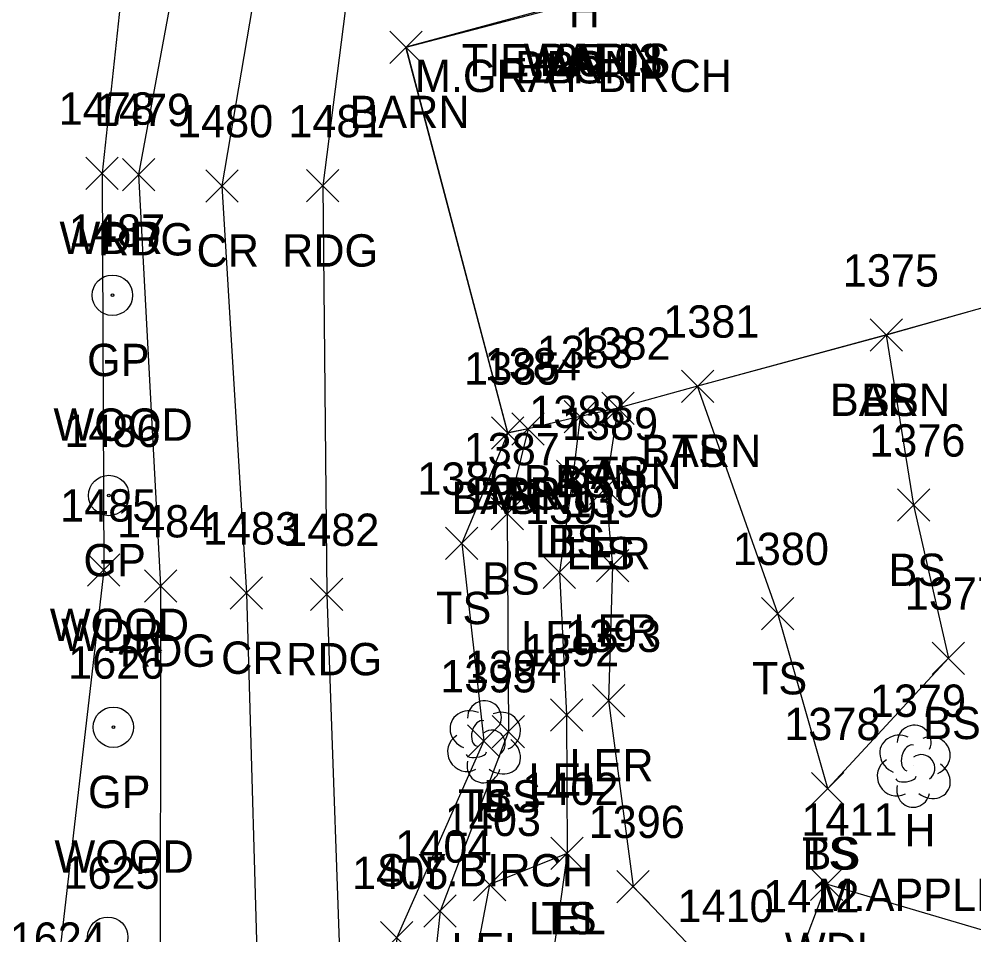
# Model space of a CAD drawing. Extents: x 1512665 to 1513714, y 110636 to 112816.
# Drawn here: x 1513105.8 to 1513164.9, y 110851.6 to 110908.3 of the extents above; entities that cross this region are included whole.
import ezdxf

# ---------------------------------------------------------------- set-up
doc = ezdxf.new("R2010")
doc.units = 0
for name, color, linetype in [('C_C', 7, 'Continuous'), ('L_A', 7, 'Continuous'), ('L_C', 7, 'Continuous'), ('L_I', 7, 'Continuous'), ('L_TIC', 7, 'Continuous'), ('LARO', 7, 'Continuous'), ('LAWA', 7, 'Continuous'), ('LBC', 7, 'Continuous'), ('LELB', 7, 'Continuous'), ('Level 13', 7, 'Continuous'), ('LTD', 7, 'Continuous'), ('P_A', 7, 'Continuous'), ('P_I', 7, 'Continuous'), ('P_TIC', 7, 'Continuous'), ('PEU', 7, 'Continuous'), ('PRC', 7, 'Continuous'), ('R_A', 7, 'Continuous'), ('R_C', 7, 'Continuous'), ('R_I', 7, 'Continuous'), ('RGP', 7, 'Continuous')]:
    doc.layers.add(name, color=color, linetype=linetype)

msp = doc.modelspace()

# ---------------------------------------------------------------- linework, layer by layer
at = {"layer": 'L_TIC'}
for points in [[(1513128.773, 110905.51), (1513130.773, 110907.51)], [(1513130.773, 110905.51), (1513128.773, 110907.51)], [(1513128.773, 110905.51), (1513130.773, 110907.51)], [(1513130.773, 110905.51), (1513128.773, 110907.51)], [(1513109.982, 110897.719), (1513111.982, 110899.719)], [(1513111.982, 110897.719), (1513109.982, 110899.719)], [(1513158.494, 110887.706), (1513160.494, 110889.706)], [(1513160.494, 110887.706), (1513158.494, 110889.706)], [(1513158.494, 110887.706), (1513160.494, 110889.706)], [(1513160.494, 110887.706), (1513158.494, 110889.706)], [(1513146.816, 110884.548), (1513148.816, 110886.548)], [(1513148.816, 110884.548), (1513146.816, 110886.548)], [(1513146.816, 110884.548), (1513148.816, 110886.548)], [(1513148.816, 110884.548), (1513146.816, 110886.548)], [(1513141.89, 110883.183), (1513143.89, 110885.183)], [(1513143.89, 110883.183), (1513141.89, 110885.183)], [(1513141.89, 110883.183), (1513143.89, 110885.183)], [(1513143.89, 110883.183), (1513141.89, 110885.183)], [(1513139.558, 110882.667), (1513141.558, 110884.667)], [(1513141.558, 110882.667), (1513139.558, 110884.667)], [(1513139.558, 110882.667), (1513141.558, 110884.667)], [(1513141.558, 110882.667), (1513139.558, 110884.667)], [(1513135.07, 110881.644), (1513137.07, 110883.644)], [(1513137.07, 110881.644), (1513135.07, 110883.644)], [(1513135.07, 110881.644), (1513137.07, 110883.644)], [(1513137.07, 110881.644), (1513135.07, 110883.644)], [(1513136.337, 110881.904), (1513138.337, 110883.904)], [(1513138.337, 110881.904), (1513136.337, 110883.904)], [(1513136.337, 110881.904), (1513138.337, 110883.904)], [(1513138.337, 110881.904), (1513136.337, 110883.904)], [(1513139.1, 110878.963), (1513141.1, 110880.963)], [(1513141.1, 110878.963), (1513139.1, 110880.963)], [(1513139.1, 110878.963), (1513141.1, 110880.963)], [(1513141.1, 110878.963), (1513139.1, 110880.963)], [(1513141.127, 110878.225), (1513143.127, 110880.225)], [(1513143.127, 110878.225), (1513141.127, 110880.225)], [(1513141.127, 110878.225), (1513143.127, 110880.225)], [(1513143.127, 110878.225), (1513141.127, 110880.225)], [(1513160.183, 110877.191), (1513162.183, 110879.191)], [(1513162.183, 110877.191), (1513160.183, 110879.191)], [(1513135.042, 110876.657), (1513137.042, 110878.657)], [(1513137.042, 110876.657), (1513135.042, 110878.657)], [(1513132.23, 110874.829), (1513134.23, 110876.829)], [(1513134.23, 110874.829), (1513132.23, 110876.829)], [(1513110.08, 110873.171), (1513112.08, 110875.171)], [(1513112.08, 110873.171), (1513110.08, 110875.171)], [(1513141.558, 110873.446), (1513143.558, 110875.446)], [(1513143.558, 110873.446), (1513141.558, 110875.446)], [(1513138.267, 110873.032), (1513140.267, 110875.032)], [(1513140.267, 110873.032), (1513138.267, 110875.032)], [(1513151.775, 110870.485), (1513153.775, 110872.485)], [(1513153.775, 110870.485), (1513151.775, 110872.485)], [(1513162.332, 110867.72), (1513164.332, 110869.72)], [(1513164.332, 110867.72), (1513162.332, 110869.72)], [(1513141.308, 110865.107), (1513143.308, 110867.107)], [(1513143.308, 110865.107), (1513141.308, 110867.107)], [(1513138.714, 110864.221), (1513140.714, 110866.221)], [(1513140.714, 110864.221), (1513138.714, 110866.221)], [(1513135.12, 110863.188), (1513137.12, 110865.188)], [(1513137.12, 110863.188), (1513135.12, 110865.188)], [(1513133.591, 110862.608), (1513135.591, 110864.608)], [(1513135.591, 110862.608), (1513133.591, 110864.608)], [(1513154.872, 110859.655), (1513156.872, 110861.655)], [(1513156.872, 110859.655), (1513154.872, 110861.655)], [(1513154.872, 110859.655), (1513156.872, 110861.655)], [(1513156.872, 110859.655), (1513154.872, 110861.655)], [(1513138.746, 110855.646), (1513140.746, 110857.646)], [(1513140.746, 110855.646), (1513138.746, 110857.646)], [(1513138.746, 110855.646), (1513140.746, 110857.646)], [(1513140.746, 110855.646), (1513138.746, 110857.646)], [(1513133.95, 110853.724), (1513135.95, 110855.724)], [(1513135.95, 110853.724), (1513133.95, 110855.724)], [(1513154.8, 110853.743), (1513156.8, 110855.743)], [(1513156.8, 110853.743), (1513154.8, 110855.743)], [(1513142.826, 110853.603), (1513144.826, 110855.603)], [(1513144.826, 110853.603), (1513142.826, 110855.603)], [(1513130.893, 110852.079), (1513132.893, 110854.079)], [(1513132.893, 110852.079), (1513130.893, 110854.079)], [(1513128.213, 110850.444), (1513130.213, 110852.444)], [(1513130.213, 110850.444), (1513128.213, 110852.444)]]:
    msp.add_lwpolyline(points, dxfattribs=at)
at = {"layer": 'LARO'}
for points in [[(1513140.1, 110879.963), (1513139.267, 110874.032), (1513139.714, 110865.221), (1513139.746, 110856.646), (1513134.95, 110854.724), (1513132.21, 110840.272), (1513133.616, 110832.794), (1513134.843, 110824.823), (1513139.129, 110826.282)], [(1513142.127, 110879.225), (1513142.558, 110874.446), (1513142.308, 110866.107), (1513143.826, 110854.603), (1513148.788, 110849.402), (1513154.003, 110849.999), (1513164.386, 110843.715), (1513159.063, 110832.169), (1513158.033, 110824.358), (1513152.454, 110822.764), (1513147.819, 110826.13), (1513139.129, 110826.282)]]:
    msp.add_lwpolyline(points, dxfattribs=at)
at = {"layer": 'LAWA'}
for points in [[(1513113.578, 110922.99), (1513110.982, 110898.719), (1513111.08, 110874.171), (1513108.004, 110847.38), (1513106.159, 110836.973), (1513101.969, 110832.474), (1513101.106, 110831.183), (1513095.313, 110829.256)], [(1513169.909, 110850.574), (1513155.8, 110854.743), (1513154.003, 110849.999), (1513151.762, 110839.769), (1513150.998, 110833.435), (1513152.454, 110822.764), (1513150.034, 110815.279), (1513136.759, 110804.589), (1513129.365, 110796.508), (1513125.79, 110797.836), (1513115.011, 110789.722), (1513110.226, 110788.604), (1513101.86, 110785.924), (1513106.089, 110777.421), (1513109.383, 110771.51), (1513113.636, 110761.19), (1513120.116, 110747.897), (1513117.812, 110736.666), (1513111.118, 110720.921), (1513118.271, 110709.907)]]:
    msp.add_lwpolyline(points, dxfattribs=at)
at = {"layer": 'LBC'}
for points in [[(1513141.517, 110909.732), (1513161.13, 110914.731), (1513177.091, 110919.233), (1513179.116, 110918.457), (1513186.213, 110896.595), (1513183.81, 110895.789), (1513180.342, 110894.907), (1513175.354, 110893.195), (1513159.494, 110888.706), (1513147.816, 110885.548), (1513142.89, 110884.183), (1513140.558, 110883.667), (1513137.337, 110882.904), (1513136.07, 110882.644), (1513129.773, 110906.51)], [(1513141.517, 110909.732), (1513140.02, 110909.272), (1513129.773, 110906.51)]]:
    msp.add_lwpolyline(points, dxfattribs=at)
at = {"layer": 'LELB'}
for points in [[(1513159.494, 110888.706), (1513161.183, 110878.191), (1513163.332, 110868.72), (1513155.872, 110860.655)], [(1513155.872, 110860.655), (1513152.775, 110871.485), (1513147.816, 110885.548)], [(1513142.89, 110884.183), (1513142.127, 110879.225)], [(1513140.558, 110883.667), (1513140.1, 110879.963)], [(1513137.337, 110882.904), (1513136.042, 110877.657), (1513136.12, 110864.188), (1513131.893, 110853.079), (1513130.46, 110839.891), (1513131.567, 110832.675), (1513130.921, 110819.726), (1513129.422, 110808.1), (1513125.79, 110797.836), (1513116.71, 110786.148), (1513110.55, 110779.591), (1513106.089, 110777.421)], [(1513136.07, 110882.644), (1513133.23, 110875.829), (1513134.591, 110863.608), (1513129.213, 110851.444), (1513128.452, 110839.982), (1513129.607, 110832.324), (1513129.65, 110820.521), (1513127.768, 110809.822), (1513123.727, 110800.329), (1513115.011, 110789.722)], [(1513139.746, 110856.646), (1513137.613, 110841.281), (1513136.029, 110834.064), (1513139.129, 110826.282)]]:
    msp.add_lwpolyline(points, dxfattribs=at)
at = {"layer": 'Level 13'}
for p, q in [((1513129.783, 110906.512), (1513161.132, 110914.72)), ((1513136.079, 110882.654), (1513129.783, 110906.512)), ((1513175.352, 110893.204), (1513159.496, 110888.714)), ((1513159.496, 110888.714), (1513147.816, 110885.557)), ((1513147.816, 110885.557), (1513142.887, 110884.192)), ((1513142.887, 110884.192), (1513140.554, 110883.676)), ((1513140.554, 110883.676), (1513137.339, 110882.913)), ((1513137.339, 110882.913), (1513136.079, 110882.654))]:
    msp.add_line(p, q, dxfattribs=at)
at = {"layer": 'LTD'}
for p, q in [((1513134.591, 110863.608), (1513134.591, 110863.608)), ((1513134.591, 110863.608), (1513134.591, 110863.608)), ((1513161.174, 110862.096), (1513161.174, 110862.096)), ((1513161.174, 110862.096), (1513161.174, 110862.096))]:
    msp.add_line(p, q, dxfattribs=at)
for centre in [(1513134.638, 110865.042), (1513161.221, 110863.53)]:
    msp.add_arc(centre, 1.047, 335.52715, 180.95627, dxfattribs=at)
for centre, major_axis, ratio, start_param, end_param in [((1513133.8, 110864.275), (1.21, -0.512), 0.895232, 1.570796, 4.712389), ((1513135.633, 110864.192), (-1.141, -0.483), 0.949671, 1.570796, 4.712389), ((1513134.383, 110864.066), (-0.208, -0.792), 0.645439, 3.141593, 6.283185), ((1513133.508, 110862.9), (0.584, -1.042), 0.959034, 3.141593, 6.283185), ((1513135.091, 110863.442), (-0.5, 0.667), 0.989748, 3.141593, 6.283185), ((1513160.382, 110862.762), (1.21, -0.512), 0.895232, 1.570796, 4.712389), ((1513162.216, 110862.679), (-1.141, -0.483), 0.949671, 1.570796, 4.712389), ((1513135.591, 110862.775), (-1.09, 0.792), 0.841452, 1.570796, 4.712389), ((1513160.966, 110862.554), (-0.208, -0.792), 0.645439, 3.141593, 6.283185), ((1513134.133, 110862.858), (-0.625, -0.083), 0.423636, 0, 3.141593), ((1513161.674, 110861.929), (-0.5, 0.667), 0.989748, 3.141593, 6.283185), ((1513134.592, 110862.108), (0.265, 1.061), 0.942809, 1.570796, 4.712389), ((1513160.091, 110861.387), (0.584, -1.042), 0.959034, 3.141593, 6.283185), ((1513162.174, 110861.263), (-1.09, 0.792), 0.841452, 1.570796, 4.712389), ((1513160.716, 110861.346), (-0.625, -0.083), 0.423636, 0, 3.141593), ((1513161.174, 110860.596), (0.265, 1.061), 0.942809, 1.570796, 4.712389)]:
    msp.add_ellipse(centre, major_axis=major_axis, ratio=ratio, start_param=start_param, end_param=end_param, dxfattribs=at)
at = {"layer": 'P_TIC'}
for points in [[(1513112.236, 110897.634), (1513114.236, 110899.634)], [(1513114.236, 110897.634), (1513112.236, 110899.634)], [(1513117.394, 110896.939), (1513119.394, 110898.939)], [(1513119.394, 110896.939), (1513117.394, 110898.939)], [(1513123.626, 110896.943), (1513125.626, 110898.943)], [(1513125.626, 110896.943), (1513123.626, 110898.943)], [(1513113.597, 110872.193), (1513115.597, 110874.193)], [(1513115.597, 110872.193), (1513113.597, 110874.193)], [(1513118.913, 110871.756), (1513120.913, 110873.756)], [(1513120.913, 110871.756), (1513118.913, 110873.756)], [(1513123.876, 110871.667), (1513125.876, 110873.667)], [(1513125.876, 110871.667), (1513123.876, 110873.667)]]:
    msp.add_lwpolyline(points, dxfattribs=at)
at = {"layer": 'PEU'}
for points in [[(1513166.519, 110981.347), (1513152.909, 110972.975), (1513141.651, 110962.521), (1513132.856, 110956.743), (1513121.044, 110940.287), (1513117.581, 110922.155), (1513113.236, 110898.634), (1513114.597, 110873.193), (1513114.571, 110845.124), (1513110.002, 110827.884), (1513105.721, 110820.37), (1513100.887, 110809.465), (1513086.517, 110797.2)], [(1513170.256, 110966.545), (1513161.211, 110960.303), (1513151.369, 110951.546), (1513143.018, 110943.811), (1513133.251, 110931.043), (1513127.426, 110919.762), (1513124.626, 110897.943), (1513124.876, 110872.667), (1513125.902, 110844.176), (1513126.27, 110821.797), (1513120.028, 110808.377), (1513110.828, 110798.027), (1513092.487, 110788.311), (1513089.551, 110792.994), (1513086.517, 110797.2)]]:
    msp.add_lwpolyline(points, dxfattribs=at)
at = {"layer": 'PRC'}
msp.add_lwpolyline([(1513199.52, 110982.675), (1513185.86, 110980.154), (1513168.393, 110974.825), (1513156.296, 110966.817), (1513145.568, 110957.841), (1513135.79, 110952.04), (1513127.966, 110935.792), (1513122.325, 110921.104), (1513118.394, 110897.939), (1513119.913, 110872.756), (1513120.726, 110844.828), (1513118.948, 110825.045), (1513112.521, 110813.651), (1513105.713, 110804.091), (1513089.551, 110792.994)], dxfattribs=at)
at = {"layer": 'RGP'}
for p, q in [((1513111.618, 110891.17), (1513111.618, 110891.17)), ((1513111.392, 110878.788), (1513111.392, 110878.788)), ((1513111.678, 110864.455), (1513111.678, 110864.455))]:
    msp.add_line(p, q, dxfattribs=at)
for centre, radius in [((1513111.618, 110891.17), 1.25), ((1513111.618, 110891.17), 0.0833), ((1513111.392, 110878.788), 1.25), ((1513111.392, 110878.788), 0.0833), ((1513111.678, 110864.455), 1.25), ((1513111.678, 110864.455), 0.0833), ((1513111.331, 110851.463), 1.25)]:
    msp.add_circle(centre, radius, dxfattribs=at)

# ---------------------------------------------------------------- texts
at = {"layer": 'C_C'}
msp.add_text('TIE=25.03', height=2, dxfattribs=at).set_placement((1513133.234, 110904.715))
at = {"layer": 'L_A'}
for s, p in [('H', (1513139.844, 110907.74)), ('WALLS', (1513137.061, 110904.732)), ('BARN', (1513138.029, 110904.732)), ('BARN', (1513138.029, 110904.732)), ('BARN', (1513136.532, 110904.272)), ('BS', (1513138.461, 110904.272)), ('BARN', (1513126.284, 110901.51)), ('BARN', (1513126.284, 110901.51)), ('WDR', (1513108.344, 110893.719)), ('BARN', (1513156.006, 110883.706)), ('BS', (1513157.935, 110883.706)), ('BARN', (1513144.328, 110880.548)), ('TS', (1513146.225, 110880.548)), ('BARN', (1513139.402, 110879.183)), ('TS', (1513141.3, 110879.183)), ('BARN', (1513137.07, 110878.667)), ('BS', (1513138.999, 110878.667)), ('BARN', (1513133.848, 110877.904)), ('BS', (1513135.778, 110877.904)), ('BARN', (1513132.582, 110877.644)), ('TS', (1513134.479, 110877.644)), ('LEL', (1513137.738, 110874.963)), ('BS', (1513138.541, 110874.963)), ('LER', (1513139.71, 110874.225)), ('TS', (1513140.537, 110874.225)), ('BS', (1513159.624, 110873.191)), ('BS', (1513134.483, 110872.657)), ('TS', (1513131.64, 110870.829)), ('WDR', (1513108.442, 110869.171)), ('LEL', (1513136.905, 110869.032)), ('LER', (1513140.14, 110869.446)), ('TS', (1513151.184, 110866.485)), ('BS', (1513161.773, 110863.72)), ('LER', (1513139.891, 110861.107)), ('LEL', (1513137.352, 110860.221)), ('BS', (1513134.561, 110859.188)), ('TS', (1513133.001, 110858.608)), ('H', (1513134.024, 110858.608)), ('H', (1513160.607, 110857.096)), ('TS', (1513154.281, 110855.655)), ('BS', (1513154.313, 110855.655)), ('LEL', (1513137.384, 110851.646)), ('TS', (1513138.156, 110851.646)), ('LEL', (1513132.588, 110849.724)), ('WDL', (1513153.217, 110849.743))]:
    msp.add_text(s, height=2, dxfattribs=at).set_placement(p)
at = {"layer": 'L_C'}
for s, p in [('M.GRAY BIRCH', (1513130.332, 110903.74)), ('S.Y.BIRCH', (1513127.977, 110854.608)), ('M.APPLE', (1513155.237, 110853.096))]:
    msp.add_text(s, height=2, dxfattribs=at).set_placement(p)
at = {"layer": 'L_I'}
for s, p in [('1478', (1513108.289, 110901.719)), ('1375', (1513156.801, 110891.706)), ('1375', (1513156.801, 110891.706)), ('1381', (1513145.69, 110888.548)), ('1381', (1513145.69, 110888.548)), ('1382', (1513140.197, 110887.183)), ('1382', (1513140.197, 110887.183)), ('1383', (1513137.865, 110886.667)), ('1383', (1513137.865, 110886.667)), ('1385', (1513133.377, 110885.644)), ('1385', (1513133.377, 110885.644)), ('1384', (1513134.644, 110885.904)), ('1384', (1513134.644, 110885.904)), ('1388', (1513137.407, 110882.963)), ('1388', (1513137.407, 110882.963)), ('1389', (1513139.427, 110882.225)), ('1389', (1513139.427, 110882.225)), ('1376', (1513158.435, 110881.191)), ('1387', (1513133.349, 110880.657)), ('1386', (1513130.482, 110878.829)), ('1390', (1513139.778, 110877.446)), ('1485', (1513108.387, 110877.171)), ('1391', (1513137.141, 110877.032)), ('1380', (1513149.995, 110874.485)), ('1377', (1513160.639, 110871.72)), ('1393', (1513139.615, 110869.107)), ('1392', (1513137.021, 110868.221)), ('1395', (1513131.898, 110866.608)), ('1395', (1513131.898, 110866.608)), ('1394', (1513133.427, 110867.188)), ('1379', (1513158.473, 110865.096)), ('1378', (1513153.179, 110863.655)), ('1378', (1513153.179, 110863.655)), ('1402', (1513136.974, 110859.646)), ('1402', (1513136.974, 110859.646)), ('1403', (1513132.178, 110857.724)), ('1396', (1513141.078, 110857.603)), ('1411', (1513154.241, 110857.743)), ('1404', (1513129.121, 110856.079)), ('1405', (1513126.442, 110854.444)), ('1412', (1513151.877, 110852.999)), ('1412', (1513151.877, 110852.999)), ('1410', (1513146.575, 110852.402)), ('1624', (1513105.264, 110850.38))]:
    msp.add_text(s, height=2, dxfattribs=at).set_placement(p)
at = {"layer": 'P_A'}
for s, p in [('RDG', (1513110.724, 110893.634)), ('CR', (1513116.827, 110892.939)), ('RDG', (1513122.114, 110892.943)), ('RDG', (1513112.085, 110868.193)), ('CR', (1513118.346, 110867.756)), ('RDG', (1513122.364, 110867.667))]:
    msp.add_text(s, height=2, dxfattribs=at).set_placement(p)
at = {"layer": 'P_I'}
for s, p in [('1479', (1513110.535, 110901.634)), ('1480', (1513115.615, 110900.939)), ('1481', (1513122.5, 110900.943)), ('1484', (1513111.904, 110876.193)), ('1483', (1513117.22, 110875.756)), ('1482', (1513122.183, 110875.667))]:
    msp.add_text(s, height=2, dxfattribs=at).set_placement(p)
at = {"layer": 'R_A'}
for p in [(1513110.051, 110886.17), (1513109.825, 110873.788), (1513110.111, 110859.455)]:
    msp.add_text('GP', height=2, dxfattribs=at).set_placement(p)
at = {"layer": 'R_C'}
for p in [(1513107.973, 110882.17), (1513107.746, 110869.788), (1513108.033, 110855.455)]:
    msp.add_text('WOOD', height=2, dxfattribs=at).set_placement(p)
at = {"layer": 'R_I'}
for s, p in [('1487', (1513108.925, 110894.17)), ('1486', (1513108.644, 110881.788)), ('1626', (1513108.883, 110867.455)), ('1625', (1513108.591, 110854.463))]:
    msp.add_text(s, height=2, dxfattribs=at).set_placement(p)

doc.saveas('drawing.dxf')
